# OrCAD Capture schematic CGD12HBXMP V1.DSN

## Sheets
1 Change Log: title: XM3 Gate Driver; rev: 2; note: Change Log
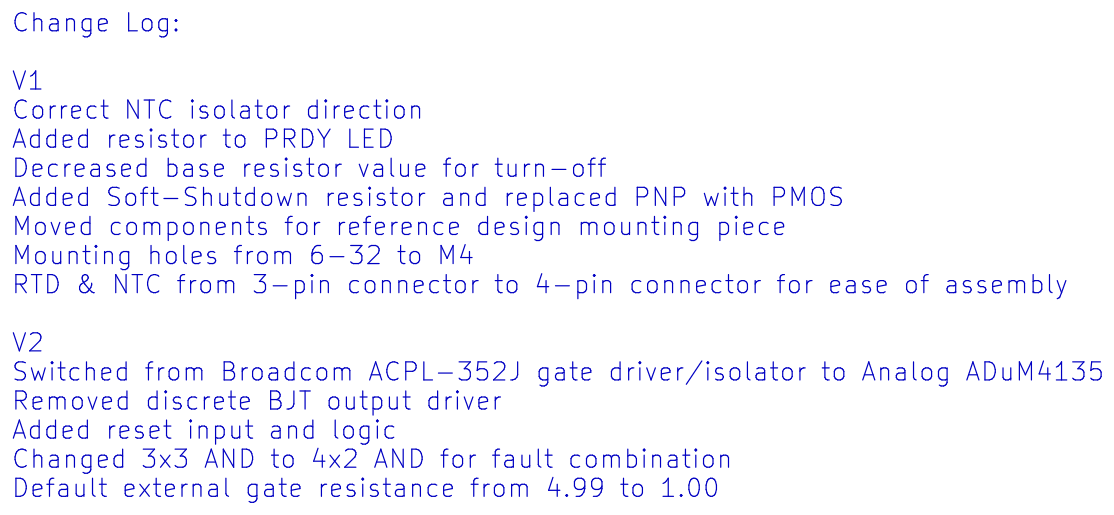
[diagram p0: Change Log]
2 RTD: size Custom; note: RTD
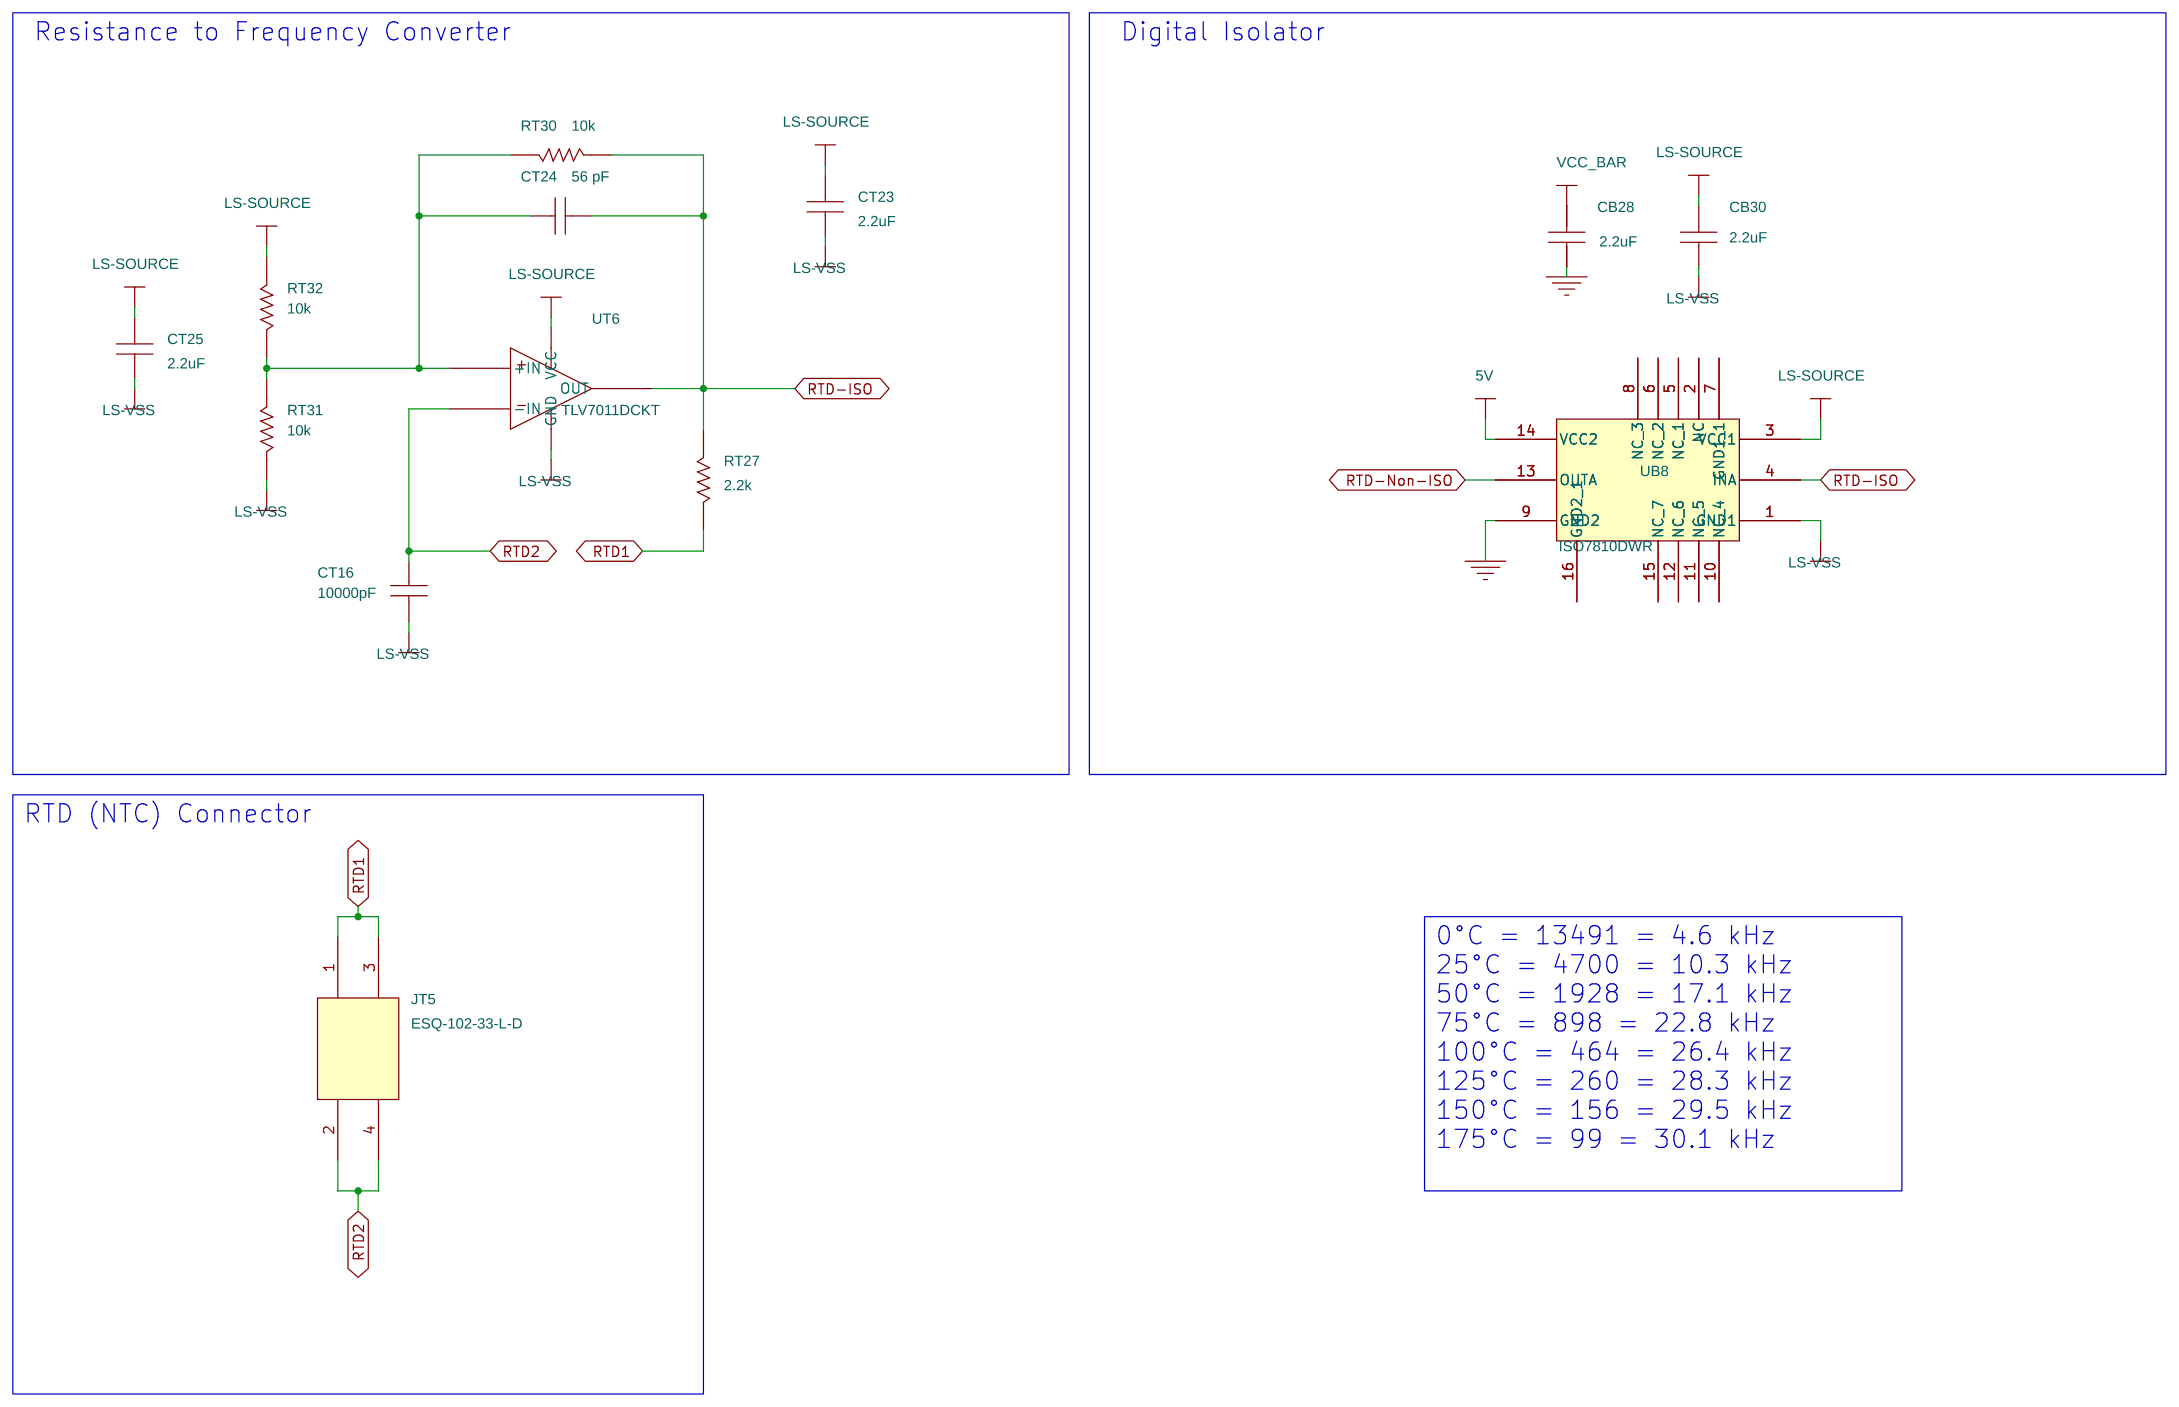
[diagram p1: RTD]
3 Differential Signaling: size B; note: Differential Signaling
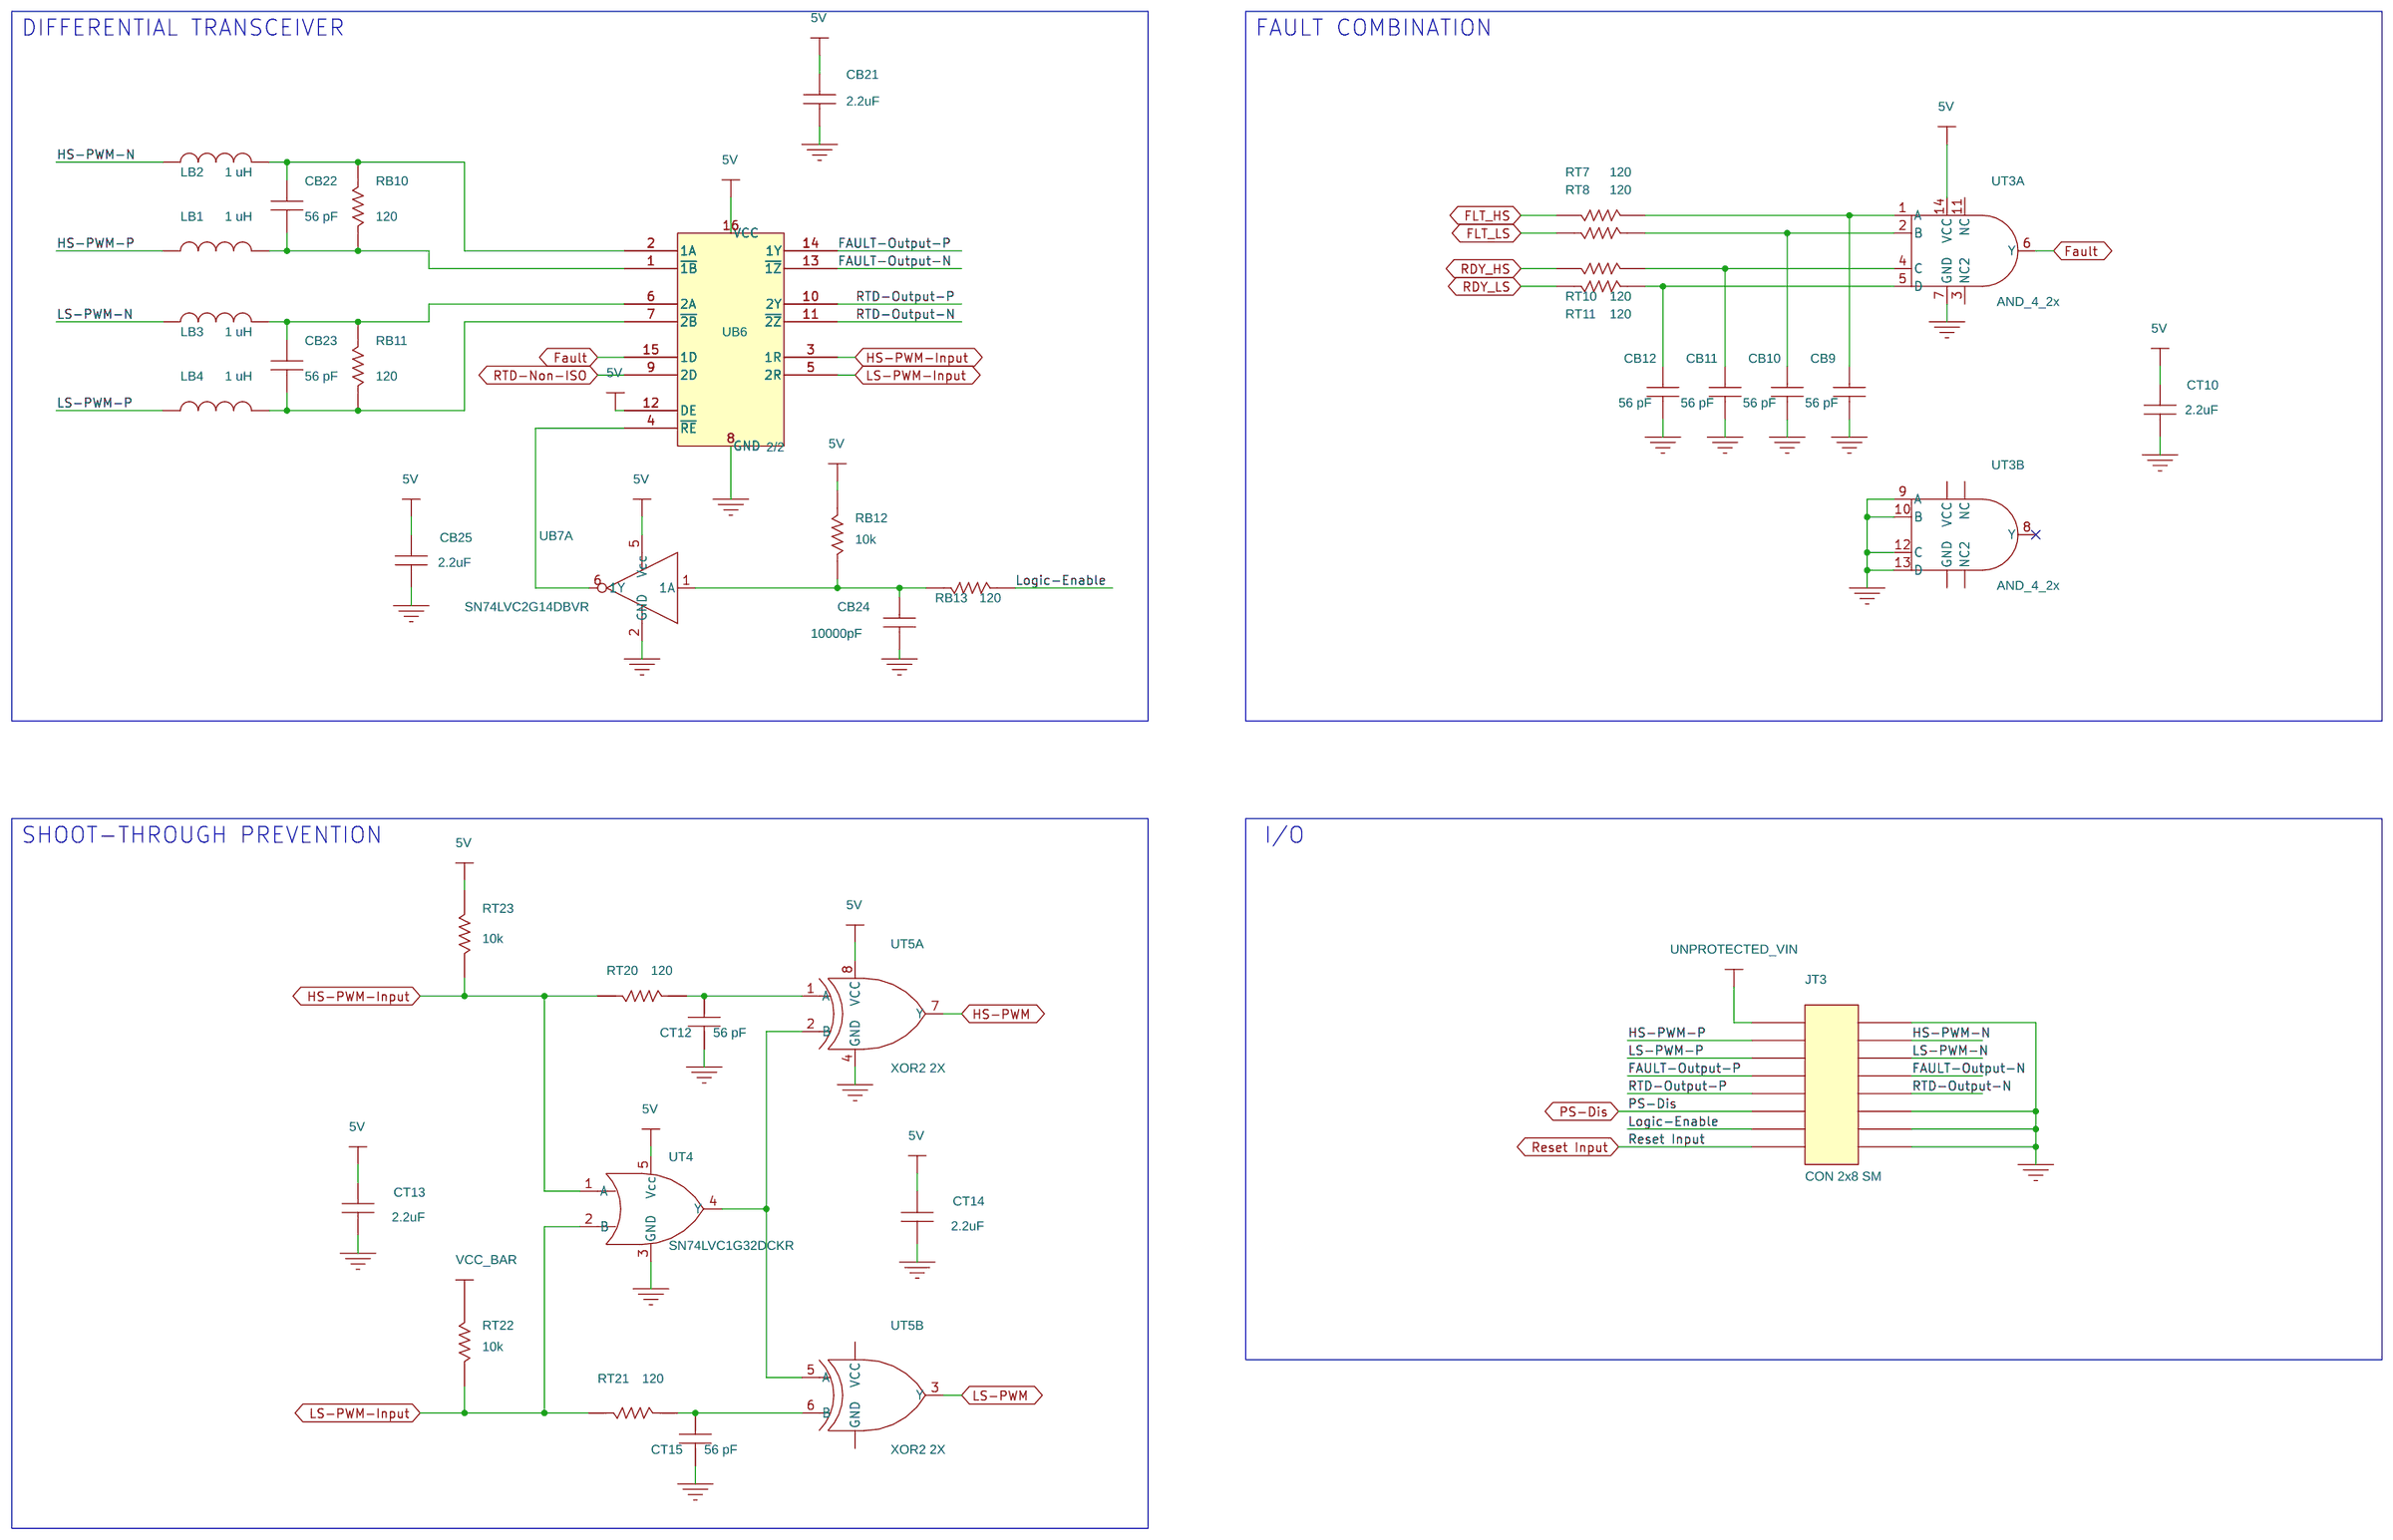
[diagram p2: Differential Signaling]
4 Power Supplies: size Custom; note: Power Supplies
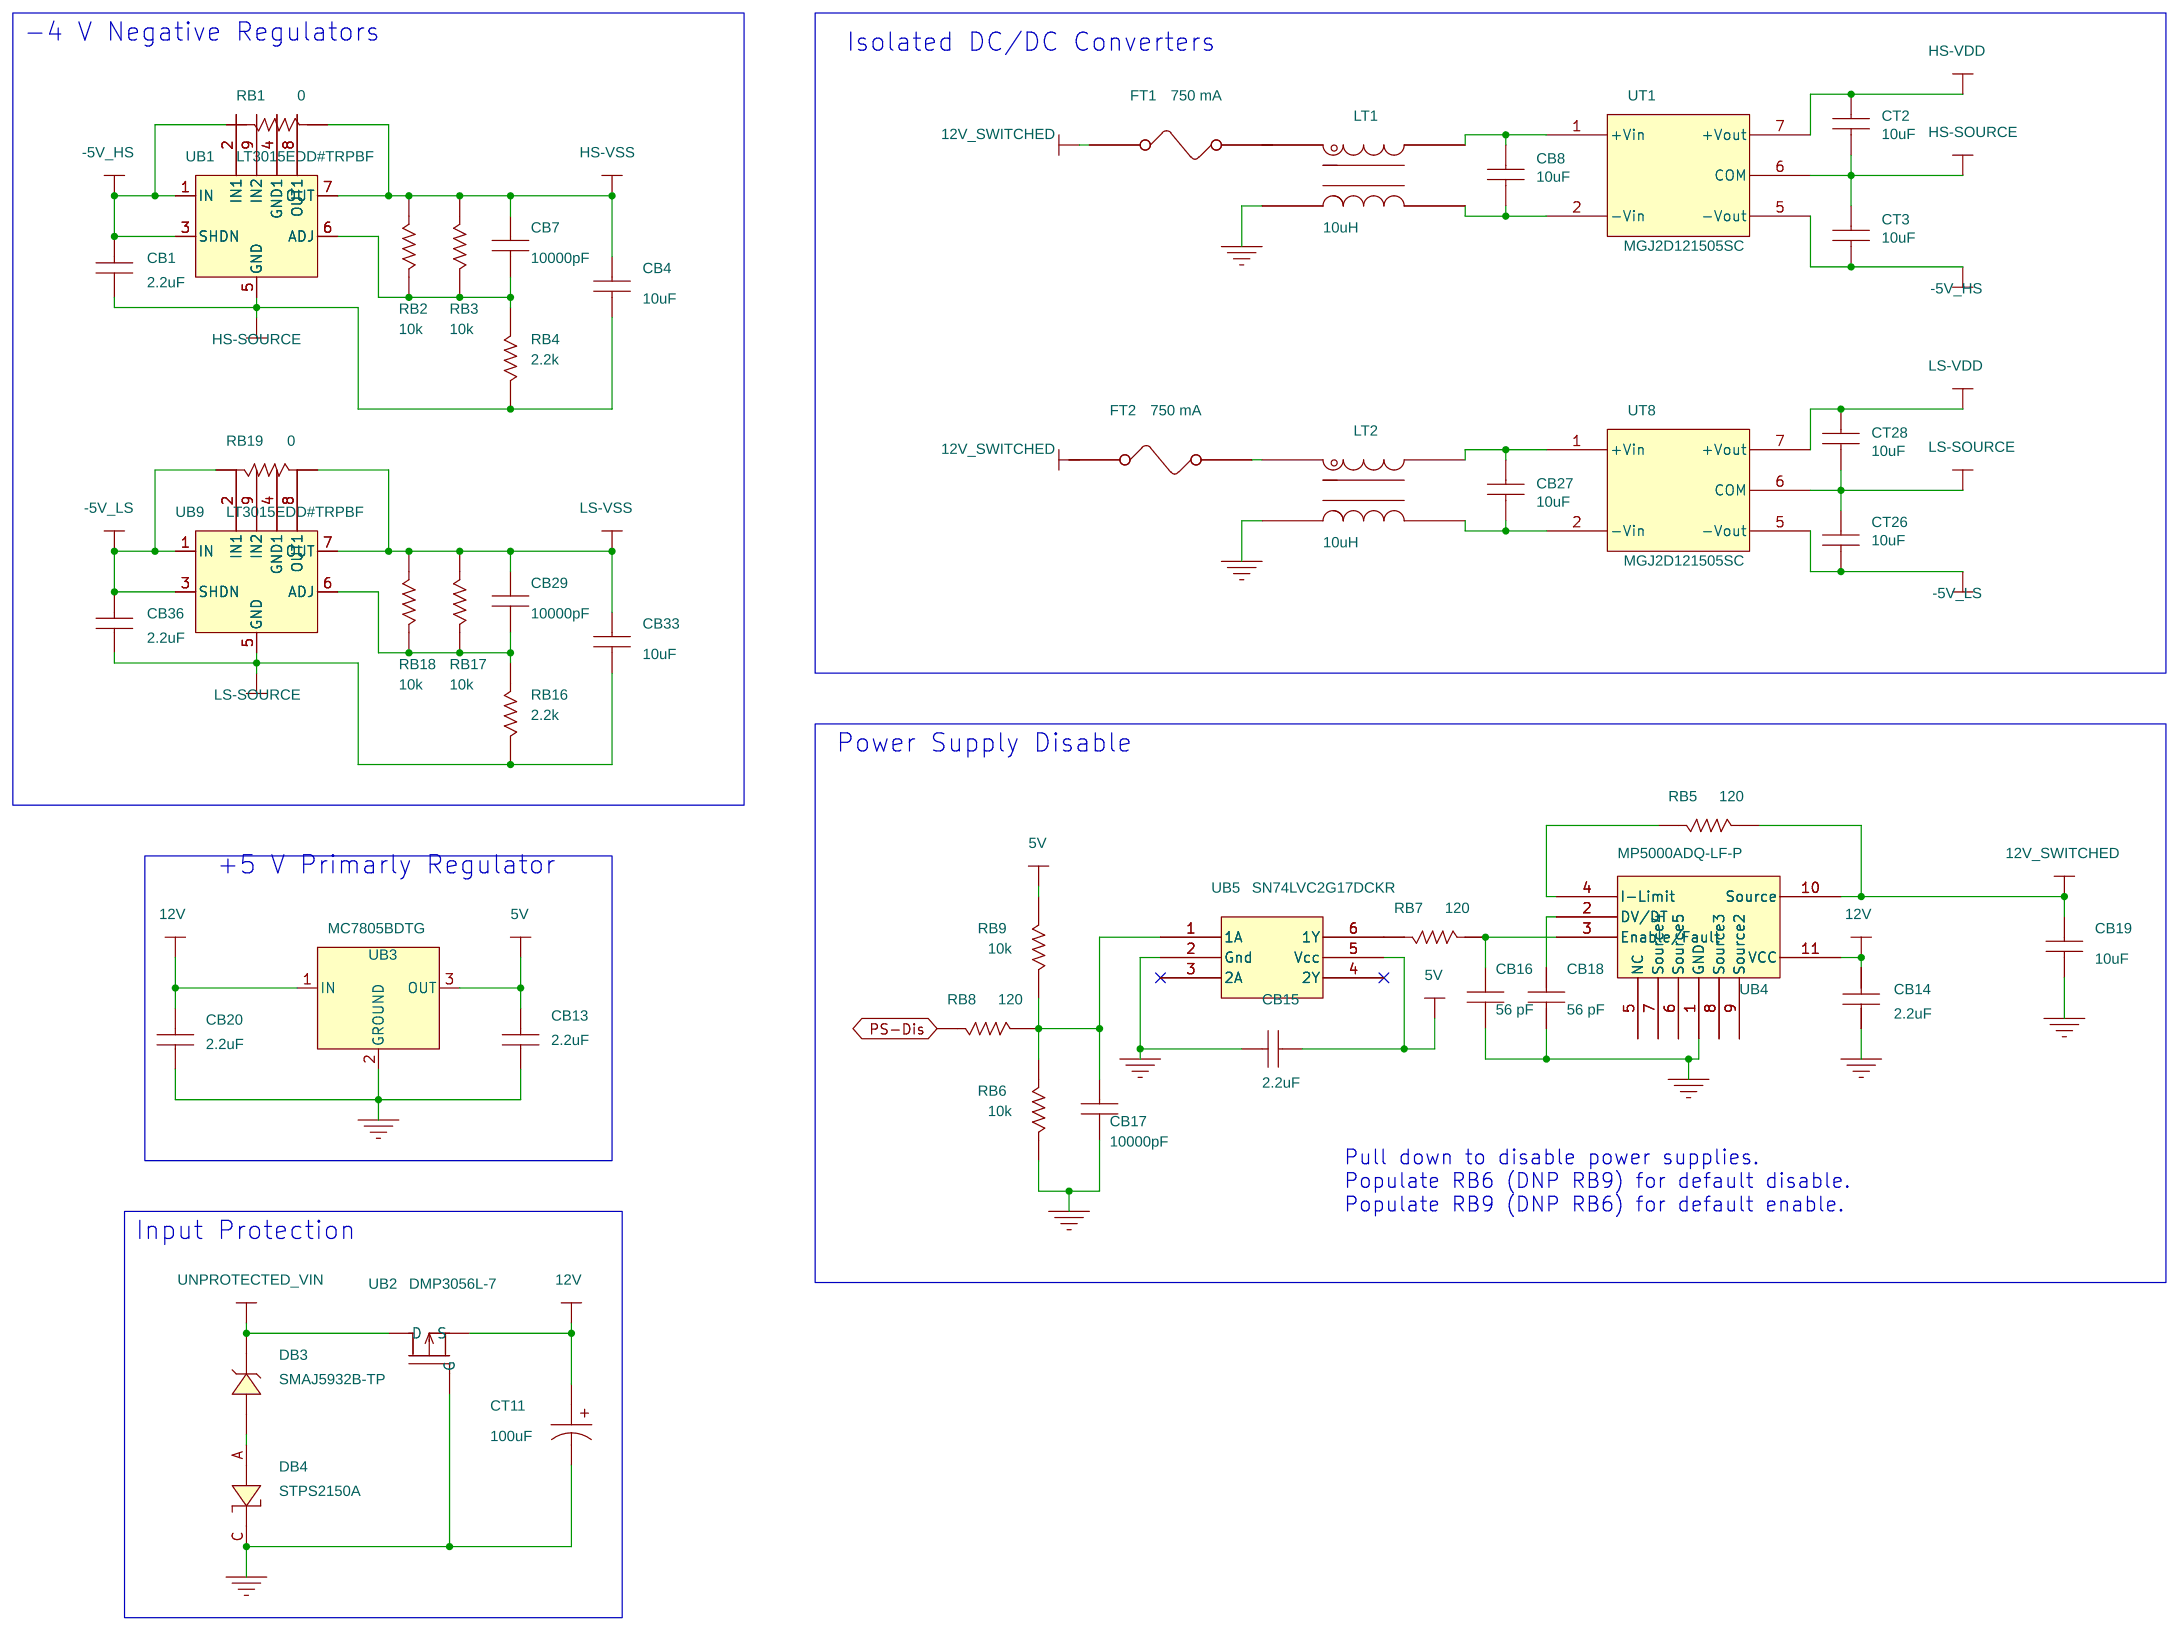
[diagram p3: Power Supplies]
5 Gate Driver: size B; note: Gate Driver
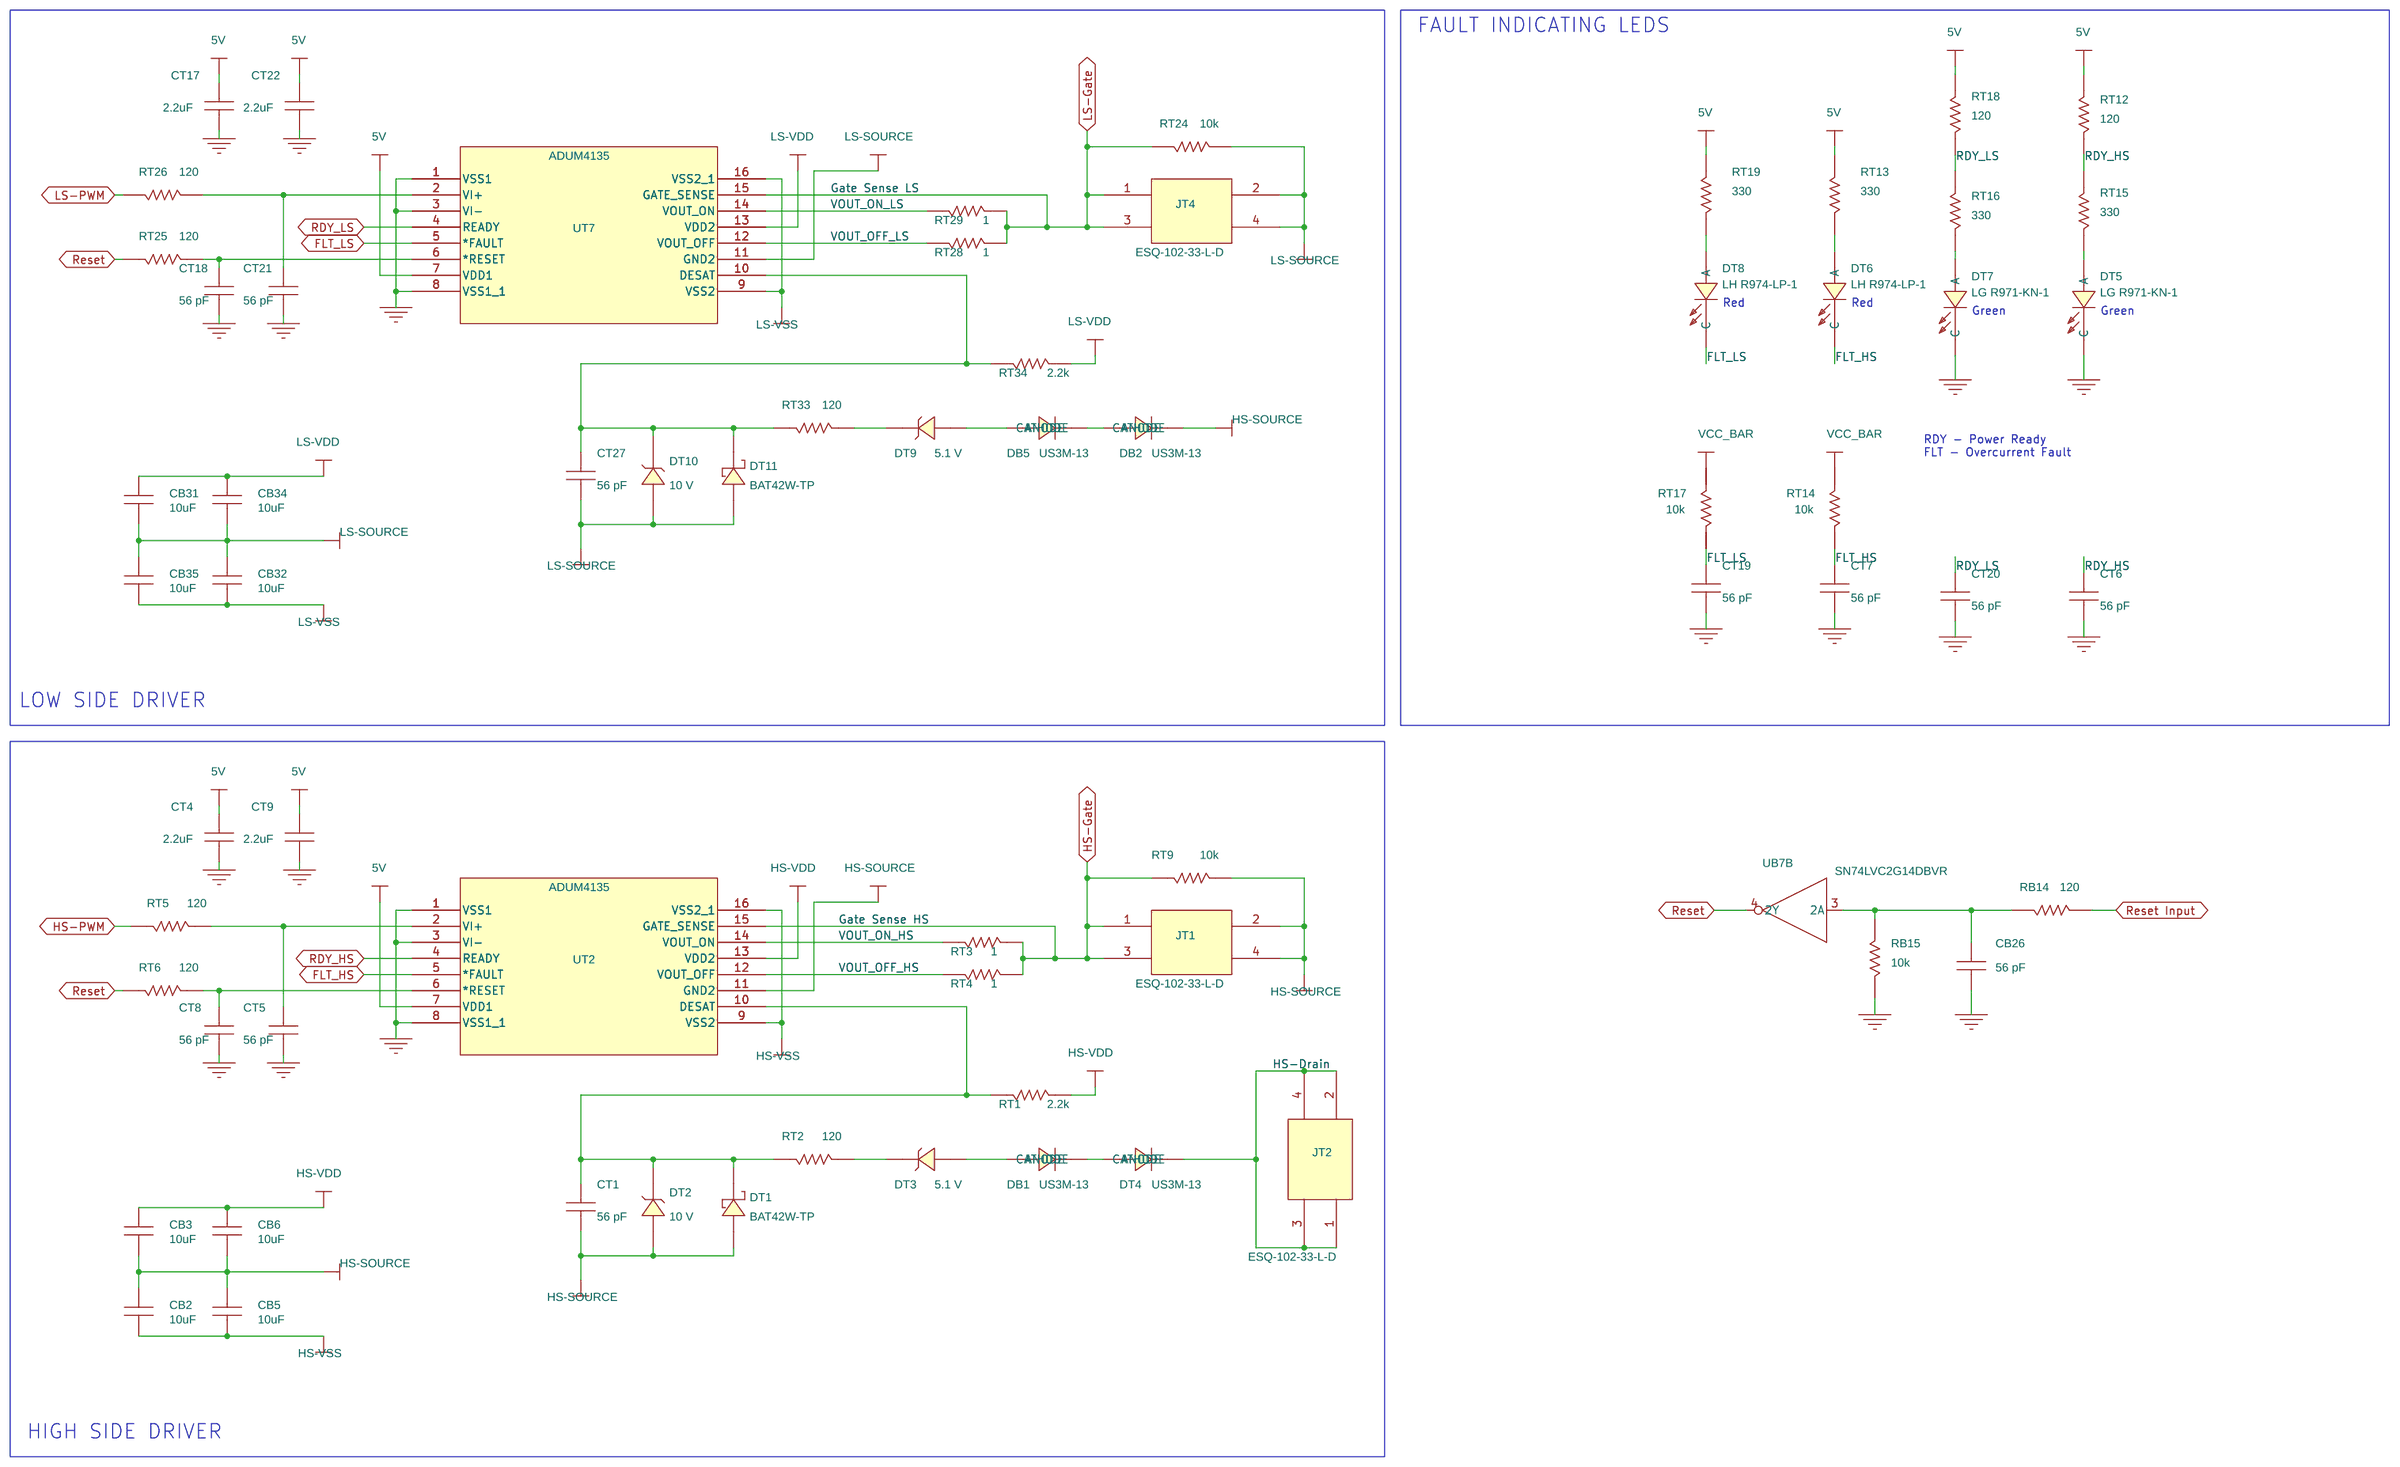
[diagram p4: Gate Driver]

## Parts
sheet Differential Signaling
CB9  56 pF  [CAPC1608X90N]
CB10  56 pF  [CAPC1608X90N]
CB11  56 pF  [CAPC1608X90N]
CB12  56 pF  [CAPC1608X90N]
CB21  2.2uF  [CAPC1608X90N]
CB22  56 pF  [CAPC1608X90N]
CB23  56 pF  [CAPC1608X90N]
CB24  10000pF  [CAPC1608X90N]
CB25  2.2uF  [CAPC1608X90N]
CT10  2.2uF  [CAPC1608X90N]
CT12  56 pF  [CAPC1608X90N]
CT13  2.2uF  [CAPC1608X90N]
CT14  2.2uF  [CAPC1608X90N]
CT15  56 pF  [CAPC1608X90N]
JT3  CON 2x8 SM  [CON_2x8_shrouded_SM]
LB1  1 uH  [INDC1608X95N]
LB2  1 uH  [INDC1608X95N]
LB3  1 uH  [INDC1608X95N]
LB4  1 uH  [INDC1608X95N]
RB10  120  [RESC1608X55N]
RB11  120  [RESC1608X55N]
RB12  10k  [RESC1608X55N]
RB13  120  [RESC1608X55N]
RT7  120  [RESC1608X55N]
RT8  120  [RESC1608X55N]
RT10  120  [RESC1608X55N]
RT11  120  [RESC1608X55N]
RT20  120  [RESC1608X55N]
RT21  120  [RESC1608X55N]
RT22  10k  [RESC1608X55N]
RT23  10k  [RESC1608X55N]
UB6  2/2  [TSSOP_16]
UB7  SN74LVC2G14DBVR  [SOT_23_6]  (sections A,B)
UT3  AND_4_2x  [D14]  (sections A,B)
UT4  SN74LVC1G32DCKR  [SC70_5]
UT5  XOR2 2X  [US8_2P40X2P10]  (sections A,B)
sheet Gate Driver
CB2  10uF  [C_1206]
CB3  10uF  [C_1206]
CB5  10uF  [C_1206]
CB6  10uF  [C_1206]
CB26  56 pF  [CAPC1608X90N]
CB31  10uF  [C_1206]
CB32  10uF  [C_1206]
CB34  10uF  [C_1206]
CB35  10uF  [C_1206]
CT1  56 pF  [CAPC1608X90N]
CT4  2.2uF  [CAPC1608X90N]
CT5  56 pF  [CAPC1608X90N]
CT6  56 pF  [CAPC1608X90N]
CT7  56 pF  [CAPC1608X90N]
CT8  56 pF  [CAPC1608X90N]
CT9  2.2uF  [CAPC1608X90N]
CT17  2.2uF  [CAPC1608X90N]
CT18  56 pF  [CAPC1608X90N]
CT19  56 pF  [CAPC1608X90N]
CT20  56 pF  [CAPC1608X90N]
CT21  56 pF  [CAPC1608X90N]
CT22  2.2uF  [CAPC1608X90N]
CT27  56 pF  [CAPC1608X90N]
DB1  US3M-13  [DO-214AB-SMC]
DB2  US3M-13  [DO-214AB-SMC]
DB5  US3M-13  [DO-214AB-SMC]
DT1  BAT42W-TP  [SOD123]
DT2  10 V  [SOD123]
DT3  5.1 V  [SOD123]
DT4  US3M-13  [DO-214AB-SMC]
DT5  LG R971-KN-1  [D_0805]
DT6  LH R974-LP-1  [D_0805]
DT7  LG R971-KN-1  [D_0805]
DT8  LH R974-LP-1  [D_0805]
DT9  5.1 V  [SOD123]
DT10  10 V  [SOD123]
DT11  BAT42W-TP  [SOD123]
JT1  ESQ-102-33-L-D  [CON_2x2_100mil_TH]
JT2  ESQ-102-33-L-D  [CON_2x2_100mil_TH]
JT4  ESQ-102-33-L-D  [CON_2x2_100mil_TH]
RB14  120  [RESC1608X55N]
RB15  10k  [RESC1608X55N]
RT1  2.2k  [RESC1608X55N]
RT2  120  [RESC1608X55N]
RT3  1  [RESC6432X70N]
RT4  1  [RESC6432X70N]
RT5  120  [RESC1608X55N]
RT6  120  [RESC1608X55N]
RT9  10k  [RESC1608X55N]
RT12  120  [RESC1608X55N]
RT13  330  [RESC1608X55N]
RT14  10k  [RESC1608X55N]
RT15  330  [RESC1608X55N]
RT16  330  [RESC1608X55N]
RT17  10k  [RESC1608X55N]
RT18  120  [RESC1608X55N]
RT19  330  [RESC1608X55N]
RT24  10k  [RESC1608X55N]
RT25  120  [RESC1608X55N]
RT26  120  [RESC1608X55N]
RT28  1  [RESC6432X70N]
RT29  1  [RESC6432X70N]
RT33  120  [RESC1608X55N]
RT34  2.2k  [RESC1608X55N]
UT2  ADUM4135  [DW0016B_N]
UT7  ADUM4135  [DW0016B_N]
sheet Power Supplies
CB1  2.2uF  [CAPC1608X90N]
CB4  10uF  [C_1206]
CB7  10000pF  [CAPC1608X90N]
CB8  10uF  [C_1206]
CB13  2.2uF  [CAPC1608X90N]
CB14  2.2uF  [CAPC1608X90N]
CB15  2.2uF  [CAPC1608X90N]
CB16  56 pF  [CAPC1608X90N]
CB17  10000pF  [CAPC1608X90N]
CB18  56 pF  [CAPC1608X90N]
CB19  10uF  [C_1206]
CB20  2.2uF  [CAPC1608X90N]
CB27  10uF  [C_1206]
CB29  10000pF  [CAPC1608X90N]
CB33  10uF  [C_1206]
CB36  2.2uF  [CAPC1608X90N]
CT2  10uF  [C_1206]
CT3  10uF  [C_1206]
CT11  100uF  [AlumElec_8mmx10_5mm]
CT26  10uF  [C_1206]
CT28  10uF  [C_1206]
DB3  SMAJ5932B-TP  [do-214ac]
DB4  STPS2150A  [do-214ac]
FT1  750 mA  [FUSE_SMD_SSQ2410]
FT2  750 mA  [FUSE_SMD_SSQ2410]
LT1  10uH  [SRF0905]
LT2  10uH  [SRF0905]
RB1  0  [RESC2012X70N]
RB2  10k  [RESC1608X55N]
RB3  10k  [RESC1608X55N]
RB4  2.2k  [RESC1608X55N]
RB5  120  [RESC1608X55N]
RB6  10k  [RESC1608X55N]
RB7  120  [RESC1608X55N]
RB8  120  [RESC1608X55N]
RB9  10k  [RESC1608X55N]
RB16  2.2k  [RESC1608X55N]
RB17  10k  [RESC1608X55N]
RB18  10k  [RESC1608X55N]
RB19  0  [RESC2012X70N]
UB1  LT3015EDD#TRPBF  [8-WDFN_Exposed_Pad]
UB2  DMP3056L-7  [SOT_23_3]
UB3  MC7805BDTG  [DPAK-3]
UB4  MP5000ADQ-LF-P  [10-VFDFN-thermal-V3_No_Via]
UB5  SN74LVC2G17DCKR  [SC70_6]
UB9  LT3015EDD#TRPBF  [8-WDFN_Exposed_Pad]
UT1  MGJ2D121505SC  [MGJ2]
UT8  MGJ2D121505SC  [MGJ2]
sheet RTD
CB28  2.2uF  [CAPC1608X90N]
CB30  2.2uF  [CAPC1608X90N]
CT16  10000pF  [CAPC1608X90N]
CT23  2.2uF  [CAPC1608X90N]
CT24  56 pF  [CAPC1608X90N]
CT25  2.2uF  [CAPC1608X90N]
JT5  ESQ-102-33-L-D  [CON_2x2_100mil_TH]
RT27  2.2k  [RESC1608X55N]
RT30  10k  [RESC1608X55N]
RT31  10k  [RESC1608X55N]
RT32  10k  [RESC1608X55N]
UB8  ISO7810DWR  [DW0016B_N]
UT6  TLV7011DCKT  [SC70_5]

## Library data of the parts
CB9-CB12 CB16 CB18 CB22 CB23 CB26 CT1 CT5-CT8 CT12 CT15 CT18-CT21 CT24 CT27 = CAP: CAP CER 56PF 50V C0G/NP0 0603; CLASS: DISCRETE; Dielectric Type: Capacitors; Manufacturer: Samsung Electro-Mechanics; Manufacturer PN: CL10C560JB8NNNC; PART_NUMBER: TMP-1515; Package Size: 0603 (1608 Metric); Temperature Coefficient: C0G, NP0; Tolerance: 5%
CB1 CB13-CB15 CB20 CB21 CB25 CB28 CB30 CB36 CT4 CT9 CT10 CT13 CT14 CT17 CT22 CT23 CT25 = CAP: CAP CER 2.2UF 50V X5R 0603; CLASS: DISCRETE; Company Part Status: Obsolete; Manufacturer: Murata Electronics North America; Manufacturer PN: GRT188R61H225ME13D; PART_NUMBER: TMP-1549; Package Size: 0603 (1608 Metric); Rated Voltage: 50V; Temperature Coefficient: X5R; Tolerance: 20%
CB7 CB17 CB24 CB29 CT16 = CAP: CAP CER 10000PF 25V 10% X7R 0603; CLASS: DISCRETE; Company Part Status: New; Dielectric Type: Capacitors; Manufacturer: Samsung Electro-Mechanics America, Inc.; Manufacturer PN: CL10B103KA8NNNC; PART_NUMBER: TMP-566; Package Size: 0603 (1608 Metric); Rated Voltage: 25V; Temperature Coefficient: X7R; Tolerance: 10%
JT3 = CON16A_Corrected: CONN HEADER SMD 16POS 2.54MM; CLASS: IO; Company Part Status: Released; Manufacturer: Sullins Connector Solutions; Manufacturer PN: SBH11-NBPC-D08-SM-BK; PART_NUMBER: TMP-1557
LB1-LB4 = INDUCTOR: FIXED IND 1UH 600MA 150 MOHM SMD; CLASS: DISCRETE; Manufacturer: TDK Corporation; Manufacturer PN: MLZ1608A1R0WT000; PART_NUMBER: TMP-1514; Package Size: 0603 (1608 Metric); Tolerance: 20%
RB5 RB7 RB8 RB10 RB11 RB13 RB14 RT7 RT8 RT10 RT11 RT20 RT21 = RES: RES SMD 120 OHM 1% 1/10W 0603; CLASS: DISCRETE; Manufacturer: Yageo; Manufacturer PN: RC0603FR-07120RL; PART_NUMBER: TMP-957; Package Size: 0603 (1608 Metric); Rated Power: 0.1W, 1/10W; Temperature Coefficient: 100ppm/C; Tolerance: 1%
RB2 RB3 RB6 RB9 RB12 RB15 RB17 RB18 RT9 RT14 RT17 RT22-RT24 RT30-RT32 = RES: RES SMD 10K OHM 1% 1/10W 0603; CLASS: DISCRETE; Company Part Status: New; Manufacturer: Panasonic Electronic Components; Manufacturer PN: ERJ-3EKF1002V; PART_NUMBER: TMP-788; Package Size: 0603 (1608 Metric); Rated Power: 0.1W, 1/10W; Temperature Coefficient: 100ppm/C; Tolerance: 1%
UB6 = SN65C1167: IC DIFF DVR/RCVR DUAL 16-TSSOP; CLASS: IC; Company Part Status: Released; Manufacturer: Texas Instruments; Manufacturer PN: SN65C1167EPWR; PART_NUMBER: TMP-1588; Package Size: 16-TSSOP (0.173", 4.40mm Width); Supply Voltage: 4.5V ~ 5.5V
UB7 = SN74LVC2G04: IC INVERTER DUAL SHMT-T SOT-23-6; CLASS: IC; Manufacturer: Texas Instruments; PART_NUMBER: TMP-658; Package Size: SOT-23-6; Supply Voltage: 1.65 V - 5.5 V
UT3 = AND4_2X: IC GATE AND 2CH 4-INP 14SOIC; CLASS: IC; Company Part Status: Released; Manufacturer: Texas Instruments; Manufacturer PN: SN74HC21DR; PART_NUMBER: TMP-1541; Package Size: 14-SOIC (0.154", 3.90mm Width); Supply Voltage: 2 V - 6 V
UT4 = SN74LVC1G32: IC GATE OR 1CH 2-INP SC-70-5; CLASS: IC; Manufacturer: Texas Instruments; PART_NUMBER: TMP-446; Package Size: 5-TSSOP, SC-70-5, SOT-353; Supply Voltage: 1.65 V - 5.5 V
UT5 = XOR2_2X: IC GATE XOR 2CH 2-INP US8; CLASS: IC; Company Part Status: Released; Manufacturer: ON Semiconductor; Manufacturer PN: NL27WZ86USG; PART_NUMBER: TMP-1551; Package Size: 8-VFSOP (0.091", 2.30mm Width); Supply Voltage: 1.65 V ~ 5.5 V
CB2-CB6 CB8 CB19 CB27 CB31-CB35 CT2 CT3 CT26 CT28 = CAP: CAP CER 10UF 16V X7R 1206; CLASS: DISCRETE; Company Part Status: New; Dielectric Type: Capacitors; Manufacturer: Murata Electronics North America; Manufacturer PN: GCM31CR71C106KA64L; PART_NUMBER: TMP-885; Package Size: 1206 (3216 Metric); Rated Voltage: 16V; Temperature Coefficient: X7R; Tolerance: 10%
DB1 DB2 DB5 DT4 = DIODE_1: DIODE GEN PURP 1KV 3A SMC; CLASS: DISCRETE; Manufacturer: Diodes Incorporated; PART_NUMBER: TMP-1412; Package Size: DO-214AB, SMC
DT1 DT11 = DIODE_SCHOTTKY_11: DIODE SCHOTTKY 30V 200MA SOD123; CLASS: DISCRETE; Company Part Status: Released; Manufacturer: Micro Commercial Co; PART_NUMBER: TMP-1535; Package Size: SOD-123; Rated Voltage: 30 V
DT2 DT10 = DIODE_ZENER_3: DIODE ZENER 10V 500MW SOD123; CLASS: DISCRETE; Manufacturer: Micro Commercial Co; Manufacturer PN: BZT52C10-TP; PART_NUMBER: TMP-1533; Package Size: SOD-123
DT3 DT9 = DIODE_ZENER_4: DIODE ZENER 5.1V 365MW SOD123; CLASS: DISCRETE; Company Part Status: New; Manufacturer: Nexperia USA Inc.; Manufacturer PN: PDZ5.1BGWJ; PART_NUMBER: TMP-1564; Package Size: SOD-123; Rated Power: 365mW; Rated Voltage: 1.1V @ 100mA
DT5 DT7 = LED: LED GREEN DIFFUSED 0805 SMD; CLASS: DISCRETE; Manufacturer: OSRAM Opto Semiconductors Inc.; PART_NUMBER: TMP-915; Package Size: 0805 (2012 Metric); Rated Voltage: 2.2V
DT6 DT8 = LED: LED RED DIFFUSED 0805 SMD; CLASS: DISCRETE; Manufacturer: OSRAM Opto Semiconductors Inc.; PART_NUMBER: TMP-917; Package Size: 0805 (2012 Metric); Rated Voltage: 1.8V @ 20mA
JT1 JT2 JT4 JT5 = CON_2x2_100mil: Flexible 25 mil SQ Board Stacker; CLASS: IO; Manufacturer: Samtec; Manufacturer PN: HW-TH-02-08-G-D-350-055; PART_NUMBER: TMP-1327
RB4 RB16 RT1 RT27 RT34 = RES: RES SMD 2.2K OHM 1% 1/10W 0603; CLASS: DISCRETE; Company Part Status: New; Manufacturer: Yageo; Manufacturer PN: RC0603FR-072K2L; PART_NUMBER: TMP-1308; Package Size: 0603 (1608 Metric); Rated Power: 0.1W, 1/10W; Temperature Coefficient: 100ppm/C; Tolerance: 1%
RT2 RT5 RT6 RT12 RT18 RT25 RT26 RT33 = RES: RES SMD 120 OHM 1% 1/10W 0603; CLASS: DISCRETE; Company Part Status: Released; Manufacturer: Yageo; Manufacturer PN: RC0603FR-07120RL; PART_NUMBER: TMP-957; Package Size: 0603 (1608 Metric); Rated Power: 0.1W, 1/10W; Temperature Coefficient: 100ppm/C; Tolerance: 1%
RT3 RT4 RT28 RT29 = RES: RES SMD 1 OHM 1% 1.5W 2512; CLASS: DISCRETE; Company Part Status: Released; Manufacturer: Vishay Dale; Manufacturer PN: CRCW25121R00FKEGHP; PART_NUMBER: TMP-1587; Package Size: 2512 (6432 Metric); Rated Power: 1.5W; Temperature Coefficient: 100ppm/C; Tolerance: 1%
RT13 RT15 RT16 RT19 = RES: RES SMD 330 OHM 5% 1/10W 0603; CLASS: DISCRETE; Company Part Status: Released; Manufacturer: Yageo; Manufacturer PN: RC0603JR-07330RL; PART_NUMBER: TMP-1554; Package Size: 0603 (1608 Metric); Rated Power: 0.1W, 1/10W; Temperature Coefficient: 100ppm/C; Tolerance: 5%
UT2 UT7 = ADUM4135BRWZ: DGTL ISO 5KV 1CH GATE DVR 16SOIC; CLASS: IC; Company Part Status: Released; Manufacturer: Analog Devices Inc.; PART_NUMBER: TMP-1586; Package Size: 16-SOIC (0.295", 7.50mm Width)
CT11 = CAP_P: CAP ALUM 100UF 20% 50V SMD; CLASS: DISCRETE; Dielectric Type: Aluminum Electrolitic; Manufacturer: Panasonic Electronic Components; Manufacturer PN: EEE-1HA101UP; PART_NUMBER: TMP-537; Package Size: Radial, Can - SMD; Tolerance: 20%
DB3 = DIODE_ZENER_3: DIODE ZENER 20V 1.5W DO214AC; CLASS: DISCRETE; Manufacturer: Micro Commercial Co; PART_NUMBER: TMP-1179; Package Size: DO-214AC, SMA; Rated Power: 1.5W; Rated Voltage: 20V
DB4 = DIODE_SCHOTTKY_13: DIODE SCHOTTKY 150V 2A SMA; CLASS: DISCRETE; Manufacturer: STMicroelectronics; PART_NUMBER: TMP-523; Package Size: DO-214AC, SMA; Rated Voltage: 820mV @ 2A
FT1 FT2 = FUSE: FUSE BOARD MNT 750MA 125VAC/VDC; CLASS: DISCRETE; Manufacturer: Bel Fuse Inc.; Manufacturer PN: SSQ 750; PART_NUMBER: TMP-1389; Package Size: 0.240" L x 0.100" W x 0.100" H (6.10mm x 2.54mm x 2.54mm)
LT1 LT2 = CM_choke_-_LPD3015_2: INDUCTOR COMMON MODE 10UH 1.6A; CLASS: DISCRETE; Manufacturer: Bourns Inc.; Manufacturer PN: SRF0905-100Y; PART_NUMBER: TMP-846; Package Size: Horizontal, 4 PC Pad
RB1 RB19 = RES: RES SMD 0 OHM JUMPER 1/8W 0805; CLASS: DISCRETE; Manufacturer: Samsung Electro-Mechanics; Manufacturer PN: RC2012J000CS; PART_NUMBER: TMP-1398; Package Size: 0805 (2012 Metric); Rated Power: 0.125W, 1/8W; Tolerance: Jumper
UB1 UB9 = LT3015: IC REG LINEAR NEG ADJ 1.5A 8DFN; CLASS: IC; Manufacturer: Linear Technology/Analog Devices; PART_NUMBER: TMP-1383; Package Size: 8-WFDFN Exposed Pad
UB2 = MOSFET_P_GSD: MOSFET P-CH 30V 4.3A SOT23; CLASS: DISCRETE; Manufacturer: Diodes Incorporated; PART_NUMBER: TMP-1395; Package Size: TO-236-3, SC-59, SOT-23-3; Polarity: P-Channel
UB3 = MC7805BDTG: IC REG LINEAR 5V 1A DPAK; CLASS: IC; Company Part Status: Released; Manufacturer: ON Semiconductor; PART_NUMBER: TMP-1562; Package Size: TO-252-3, DPak (2 Leads + Tab), SC-63
UB4 = MP5000A_5: IC CURR LIMIT SWITCH; CLASS: IC; Manufacturer: Monolithic Power Systems Inc.; PART_NUMBER: TMP-1384; Package Size: 10-VFDFN Exposed Pad; Supply Voltage: Not Required
UB5 = BUFFER_2X_6P: IC BUF NON-INVERT 5.5V SC70-6; CLASS: IC; Company Part Status: Released; Manufacturer: Texas Instruments; PART_NUMBER: TMP-1635; Package Size: 6-TSSOP, SC-88, SOT-363; Supply Voltage: 1.65V ~ 5.5V
UT1 UT8 = MGJ2: DC/DC CONVERTER 15V -5V 2W; CLASS: IC; Manufacturer: Murata Power Solutions Inc.; PART_NUMBER: TMP-1268; Package Size: 0.77" L x 0.39" W x 0.50" H (19.7mm x 10.0mm x 12.7mm); Rated Power: 2W; Supply Voltage: 10.8 - 13.2 V
UB8 = ISO7810DWR: DGTL ISO 5.7KV GEN PURP 16SOIC; CLASS: IC; Company Part Status: Released; Manufacturer: Texas Instruments; PART_NUMBER: TMP-1565; Package Size: 16-SOIC (0.295", 7.50mm Width); Supply Voltage: 2.25V ~ 5.5V
UT6 = TLV7011DCKT: SMALL SIZE, MICRO POWER, LOW VOL; CLASS: IC; Company Part Status: Released; Manufacturer: Texas Instruments; PART_NUMBER: TMP-1560; Package Size: 5-TSSOP, SC-70-5, SOT-353; Supply Voltage: 1.6 V ~ 5.5 V

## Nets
5V: CB13.2 CB15.1 CB21.1 CB25.1 CB28.2 CT4.1 CT9.1 CT10.1 CT13.1 CT14.1 CT17.1 CT22.1 RB9.1 RB12.2 RT12.2 RT13.2 RT14.1 RT17.1 RT18.2 RT19.2 RT22.2 RT23.2 UB3.3(OUT) UB5.5(Vcc) UB6.12(DE) UB6.16(VCC) UB7.5(Vcc) UB8.14(VCC2) UT2.7(VDD1) UT3.14(VCC) UT4.5(Vcc) UT5.8(VCC) UT7.7(VDD1)
12V: CB14.2 CB20.2 CT11.1 UB2.2(S) UB3.1(IN) UB4.11(VCC)
12V_Switched: CB19.1 FT1.1 FT2.1 RB5.1 UB4.10(Source)
-5V_HS: CB1.2 CT3.2 RB1.1 UB1.1(IN) UB1.3(SHDN) UT1.5(-Vout)
-5V_LS: CB36.2 CT26.2 RB19.1 UB9.1(IN) UB9.3(SHDN) UT8.5(-Vout)
0: CB9.2 CB10.2 CB11.2 CB12.2 CB13.1 CB14.1 CB15.2 CB16.2 CB17.2 CB18.2 CB19.2 CB20.1 CB21.2 CB24.2 CB25.2 CB26.2 CB28.1 CT4.2 CT5.2 CT6.2 CT7.2 CT8.2 CT9.2 CT10.2 CT11.2 CT12.2 CT13.2 CT14.2 CT15.2 CT17.2 CT18.2 CT19.2 CT20.2 CT21.2 CT22.2 DB4.C DT5.2(C) DT7.2(C) JT3.2 JT3.12 JT3.14 JT3.16 LT1.2 LT2.2 RB6.2 RB15.1 UB2.1(G) UB3.2(GROUND) UB4.1(GND) UB5.2(Gnd) UB6.8(GND) UB7.2(GND) UB8.9(GND2) UT2.1(VSS1) UT2.3(VI-) UT2.8(VSS1_1) UT3.7(GND) UT3.9(A) UT3.10(B) UT3.12(C) UT3.13(D) UT4.3(GND) UT5.4(GND) UT7.1(VSS1) UT7.3(VI-) UT7.8(VSS1_1)
Fault: UB6.15(1D) UT3.6(Y)
FAULT-Output-N: JT3.8 UB6.13(~{1Z})
FAULT-Output-P: JT3.7 UB6.14(1Y)
FLT_HS: CT7.1 DT6.2(C) RT7.1 RT14.2 UT2.5(*FAULT)
FLT_LS: CT19.1 DT8.2(C) RT8.1 RT17.2 UT7.5(*FAULT)
HS-Drain: DT4.C(CATHODE) JT2.1 JT2.2 JT2.3 JT2.4
HS-Gate: JT1.1 JT1.3 RT3.2 RT4.2 RT9.1 UT2.15(GATE_SENSE)
HS-PWM: RT5.1 UT5.7(Y)
HS-PWM-Input: RT20.1 RT23.1 UB6.3(1R) UT4.1(A)
HS-PWM-N: JT3.4 LB2.1
HS-PWM-P: JT3.3 LB1.1
HS-Source: CB1.1 CB2.1 CB3.2 CB4.2 CB5.1 CB6.2 CT1.2 CT2.2 CT3.1 DB2.C(CATHODE) DT1.A DT2.A JT1.2 JT1.4 RB4.1 RT9.2 UB1.5(GND) UT1.6(COM) UT2.11(GND2)
HS-VDD: CB3.1 CB6.1 CT2.1 RT1.2 UT1.7(+Vout) UT2.13(VDD2)
HS-VSS: CB2.2 CB4.1 CB5.2 CB7.1 RB1.2 RB2.1 RB3.1 UB1.7(OUT) UT2.9(VSS2) UT2.16(VSS2_1)
Logic-Enable: JT3.13 RB13.2
LS-Gate: JT4.1 JT4.3 RT24.1 RT28.2 RT29.2 UT7.15(GATE_SENSE)
LS-PWM: RT26.1 UT5.3(Y)
LS-PWM-Input: RT21.1 RT22.1 UB6.5(2R) UT4.2(B)
LS-PWM-N: JT3.6 LB3.1
LS-PWM-P: JT3.5 LB4.1
LS-Source: CB30.2 CB31.2 CB32.1 CB33.2 CB34.2 CB35.1 CB36.1 CT23.2 CT25.2 CT26.1 CT27.2 CT28.2 DT10.A DT11.A JT4.2 JT4.4 RB16.1 RT24.2 RT32.1 UB8.3(VCC1) UB9.5(GND) UT6.5(VCC) UT7.11(GND2) UT8.6(COM)
LS-VDD: CB31.1 CB34.1 CT28.1 RT34.2 UT7.13(VDD2) UT8.7(+Vout)
LS-VSS: CB29.1 CB30.1 CB32.2 CB33.1 CB35.2 CT16.2 CT23.1 CT25.1 RB17.1 RB18.1 RB19.2 RT31.2 UB8.1(GND1) UB9.7(OUT) UT6.2(GND) UT7.9(VSS2) UT7.16(VSS2_1)
NC: UB8.2(NC) UT3.11(NC)
NC2: UT3.3(NC2)
NC_1: UB8.5(NC_1)
NC_2: UB8.6(NC_2)
NC_3: UB8.8(NC_3)
NC_4: UB8.10(NC_4)
NC_5: UB8.11(NC_5)
NC_6: UB8.12(NC_6)
NC_7: UB8.15(NC_7)
PS-Dis: JT3.11 RB8.2
RDY_HS: CT6.1 RT10.1 RT12.1 RT15.2 UT2.4(READY)
RDY_LS: CT20.1 RT11.1 RT16.2 RT18.1 UT7.4(READY)
Reset: RT6.1 RT25.1 UB7.4(2Y)
Reset Input: JT3.15 RB14.2
RTD1: JT5.1 JT5.3 RT27.2
RTD2: CT16.1 JT5.2 JT5.4 UT6.4(-IN)
RTD-ISO: CT24.2 RT27.1 RT30.2 UB8.4(INA) UT6.1(OUT)
RTD-Non-ISO: UB6.9(2D) UB8.13(OUTA)
RTD-Output-N: JT3.10 UB6.11(~{2Z})
RTD-Output-P: JT3.9 UB6.10(2Y)
Unprotected_VIN: DB3.C JT3.1 UB2.3(D)
VOUT_OFF_HS: RT4.1 UT2.12(VOUT_OFF)
VOUT_OFF_LS: RT28.1 UT7.12(VOUT_OFF)
VOUT_ON_HS: RT3.1 UT2.14(VOUT_ON)
VOUT_ON_LS: RT29.1 UT7.14(VOUT_ON)
N5110224: CT27.1 DT10.C DT11.C RT33.1 RT34.1 UT7.10(DESAT)
N5110410: CT21.1 RT26.2 UT7.2(VI+)
N5143626: FT1.2 LT1.1
N5776744: RB5.2 UB4.4(I-Limit)
N5776884: CB18.1 UB4.2(DV/DT)
N5776892: CB17.1 RB6.1 RB8.1 RB9.2 UB5.1(1A)
N5776900: CB16.1 RB7.1 UB4.3(Enable/Fault)
N5777665: CB8.1 LT1.4 UT1.1(+Vin)
N5777737: CB8.2 LT1.3 UT1.2(-Vin)
N5778706: CB27.1 LT2.4 UT8.1(+Vin)
N5778794: CB27.2 LT2.3 UT8.2(-Vin)
N5780153: FT2.2 LT2.1
N5786131: CB22.1 LB2.2 RB10.2 UB6.2(1A)
N5786223: CB22.2 LB1.2 RB10.1 UB6.1(~{1B})
N5786329: CB23.1 LB3.2 RB11.2 UB6.6(2A)
N5786365: CB23.2 LB4.2 RB11.1 UB6.7(~{2B})
N5786573: UB6.4(~{RE}) UB7.6(1Y)
N5786769: CB24.1 RB12.1 RB13.1 UB7.1(1A)
N5791884: DT8.1(A) RT19.1
N5791888: DT6.1(A) RT13.1
N5813663: CB9.1 RT7.2 UT3.1(A)
N5829702: CT12.1 RT20.2 UT5.1(A)
N5829738: UT4.4(Y) UT5.2(B) UT5.5(A)
N5829966: CT15.1 RT21.2 UT5.6(B)
N5871306: CB11.1 RT10.2 UT3.4(C)
N5927082: DB3.A DB4.A
N5941912: CB10.1 RT8.2 UT3.2(B)
N5941952: CB12.1 RT11.2 UT3.5(D)
N5948959: CB7.2 RB2.2 RB3.2 RB4.2 UB1.6(ADJ)
N5949233: CB29.2 RB16.2 RB17.2 RB18.2 UB9.6(ADJ)
N5961728: CT24.1 RT30.1 RT31.1 RT32.2 UT6.3(+IN)
N6007380: DT7.1(A) RT16.1
N6007384: DT5.1(A) RT15.1
N6009828: DT9.C RT33.2
N6009832: DB5.A(ANODE) DT9.A
N6009836: DB2.A(ANODE) DB5.C(CATHODE)
N6024502: CB26.1 RB14.1 RB15.2 UB7.3(2A)
N6026359: CT5.1 RT5.2 UT2.2(VI+)
N6026535: CT8.1 RT6.2 UT2.6(*RESET)
N6026555: CT1.1 DT1.C DT2.C RT1.1 RT2.1 UT2.10(DESAT)
N6026735: DT3.C RT2.2
N6026739: DB1.A(ANODE) DT3.A
N6026743: DB1.C(CATHODE) DT4.A(ANODE)
N6032095: CT18.1 RT25.2 UT7.6(*RESET)
N6082014: RB7.2 UB5.6(1Y)

Not connected (* = marked no-connect by the designer): UB1 2(IN1) 4(GND1) 8(OUT1) 9(IN2); UB4 5(NC) 6(Source5) 7(Source4) 8(Source3) 9(Source2); UB5 3(2A)* 4(2Y)*; UB8 7(GND1_1) 16(GND2_1); UB9 2(IN1) 4(GND1) 8(OUT1) 9(IN2); UT3 8(Y)* GND NC NC2 VCC; UT5 GND VCC

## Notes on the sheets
sheet 1
- Change Log:
  V1
  Correct NTC isolator direction
  Added resistor to PRDY LED
  Decreased base resistor value for turn-off
  Added Soft-Shutdown resistor and replaced PNP with PMOS
  Moved components for reference design mounting piece
  Mounting holes from 6-32 to M4
  RTD & NTC from 3-pin connector to 4-pin connector for ease of assembly
  V2
  Switched from Broadcom ACPL-352J gate driver/isolator to Analog ADuM4135
  Removed discrete BJT output driver
  Added reset input and logic
  Changed 3x3 AND to 4x2 AND for fault combination
  Default external gate resistance from 4.99 to 1.00
sheet 2
- Resistance to Frequency Converter
- Digital Isolator
- RTD (NTC) Connector
- 0°C = 13491 = 4.6 kHz
  25°C = 4700 = 10.3 kHz
  50°C = 1928 = 17.1 kHz
  75°C = 898 = 22.8 kHz
  100°C = 464 = 26.4 kHz
  125°C = 260 = 28.3 kHz
  150°C = 156 = 29.5 kHz
  175°C = 99 = 30.1 kHz
sheet 3
- DIFFERENTIAL TRANSCEIVER
- FAULT COMBINATION
- SHOOT-THROUGH PREVENTION
- I/O
sheet 4
- -4 V Negative Regulators
- Isolated DC/DC Converters
- Power Supply Disable
- +5 V Primarly Regulator
- Pull down to disable power supplies.
  Populate RB6 (DNP RB9) for default disable.
  Populate RB9 (DNP RB6) for default enable.
- Input Protection
sheet 5
- FAULT INDICATING LEDS
- Red
- Red
- Green
- Green
- RDY - Power Ready
  FLT - Overcurrent Fault
- LOW SIDE DRIVER
- HIGH SIDE DRIVER
